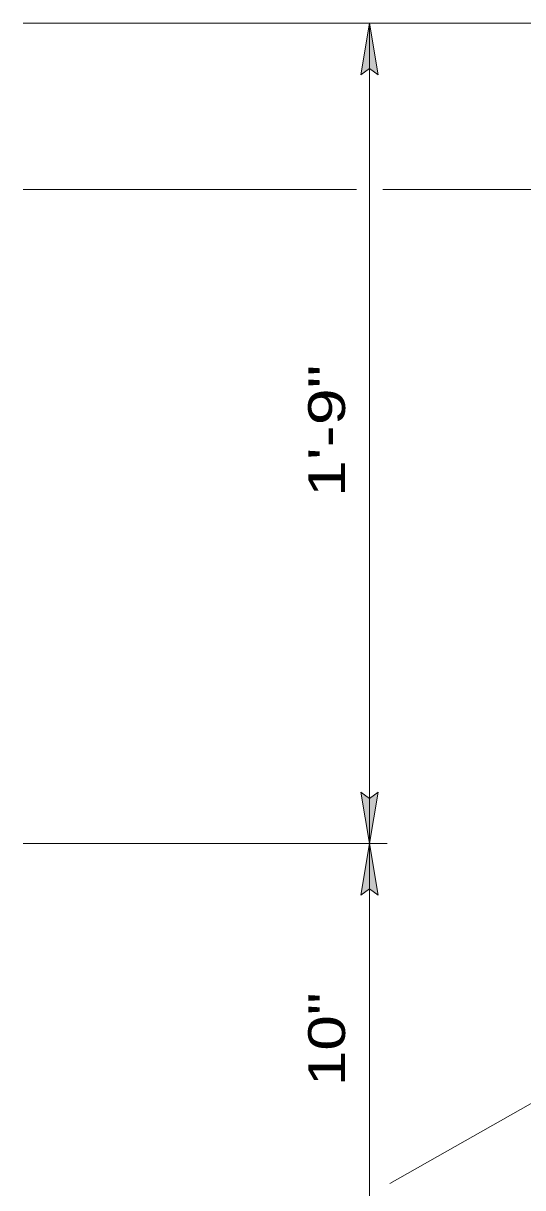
# Model space of a CAD drawing. Extents: x -9.07 to -2.08, y 8.04 to 17.77.
# Drawn here: x -5.178 to -4.365, y 14.699 to 16.597 of the extents above; entities that cross this region are included whole.
import ezdxf
from ezdxf.enums import TextEntityAlignment as Align

# ---------------------------------------------------------------- set-up
doc = ezdxf.new("R2010")
doc.units = 0
doc.header["$LTSCALE"] = 0.024
doc.layers.add('10', color=7, linetype='Continuous', lineweight=13)
doc.layers.add('12', color=7, linetype='Continuous', lineweight=53)

msp = doc.modelspace()

# ---------------------------------------------------------------- hatches: boundary and pattern name
at = {"layer": '10'}
for points in [[(-4.61433, 16.59717), (-4.62833, 16.51317), (-4.61433, 16.52367), (-4.60033, 16.51317)], [(-4.61433, 15.26), (-4.60033, 15.344), (-4.61433, 15.3335), (-4.62833, 15.344)], [(-4.61433, 15.26), (-4.60033, 15.17583), (-4.61433, 15.18633), (-4.62833, 15.17583)]]:
    msp.add_hatch(color=256, dxfattribs=at).paths.add_polyline_path(points)

# ---------------------------------------------------------------- linework, layer by layer
for p, q in [((-5.17817, 16.59717), (-4.18633, 16.59717)), ((-4.62833, 16.51317), (-4.61433, 16.59717)), ((-4.60033, 16.51317), (-4.61433, 16.59717)), ((-4.62833, 16.51317), (-4.61433, 16.52367)), ((-4.60033, 16.51317), (-4.61433, 16.52367)), ((-5.17817, 16.32633), (-4.63583, 16.32633)), ((-4.59267, 16.32633), (-4.23683, 16.32633)), ((-4.62833, 15.344), (-4.61433, 15.26)), ((-4.62833, 15.344), (-4.61433, 15.3335)), ((-4.60033, 15.344), (-4.61433, 15.26)), ((-4.60033, 15.344), (-4.61433, 15.3335)), ((-4.5855, 15.26), (-5.17817, 15.26)), ((-4.62833, 15.17583), (-4.61433, 15.26)), ((-4.60033, 15.17583), (-4.61433, 15.26)), ((-4.62833, 15.17583), (-4.61433, 15.18633)), ((-4.60033, 15.17583), (-4.61433, 15.18633)), ((-4.58117, 14.706), (-4.24567, 14.89617))]:
    msp.add_line(p, q, dxfattribs=at)
for points in [[(-4.61433, 16.59717), (-4.62833, 16.51317), (-4.61433, 16.52367), (-4.60033, 16.51317)], [(-4.61433, 15.26), (-4.60033, 15.344), (-4.61433, 15.3335), (-4.62833, 15.344)], [(-4.61433, 15.26), (-4.60033, 15.17583), (-4.61433, 15.18633), (-4.62833, 15.17583)]]:
    msp.add_lwpolyline(points, close=True, dxfattribs=at)
for points in [[(-4.61433, 15.26), (-4.61433, 16.3255), (-4.61433, 16.59717)], [(-4.61433, 14.41983), (-4.61433, 14.6115), (-4.61433, 15.26)]]:
    msp.add_lwpolyline(points, dxfattribs=at)

# ---------------------------------------------------------------- texts
at = {"layer": '12'}
for s, width, p in [('1\'-9"', 1.35, (-4.65425, 15.93275)), ('10"', 1.3, (-4.65425, 14.94083))]:
    msp.add_text(s, height=0.06001, rotation=90, dxfattribs=dict(at, width=width)).set_placement(p, align=Align.CENTER)

doc.saveas('drawing.dxf')
